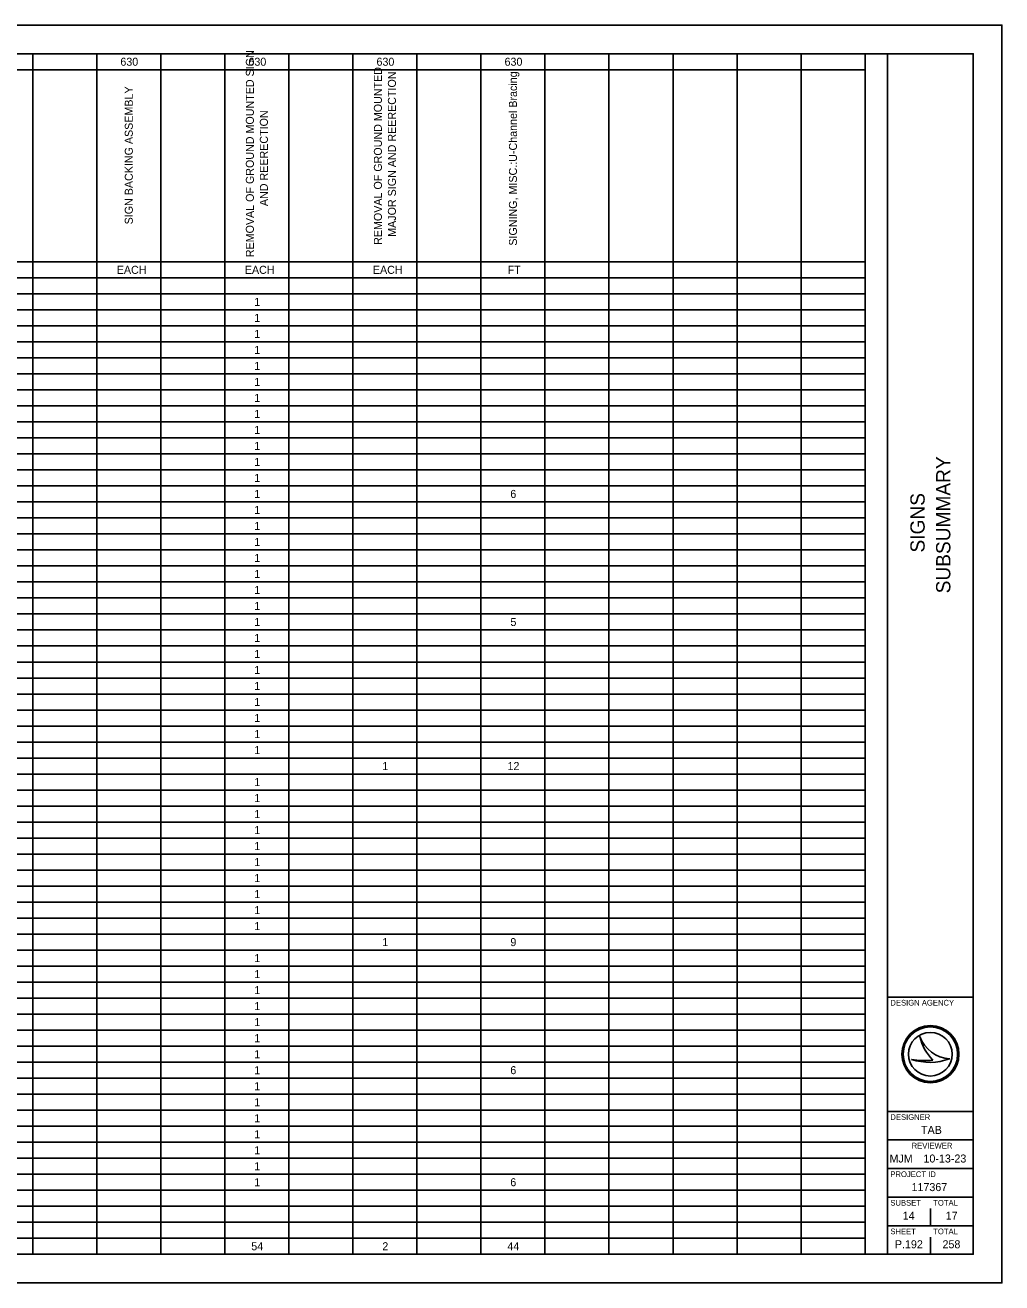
# Model space of a CAD drawing. Extents: x 0 to 34, y 0 to 22.
# Drawn here: x 16.92 to 34, y 0 to 22 of the extents above; entities that cross this region are included whole.
import ezdxf

# ---------------------------------------------------------------- set-up
doc = ezdxf.new("R2010")
doc.units = 0
for name, color, linetype in [('Default', 7, 'Continuous'), ('SH_Border', 7, 'Continuous'), ('SH_Cut_Line', 7, 'Continuous'), ('SH_Data', 7, 'Continuous')]:
    doc.layers.add(name, color=color, linetype=linetype)

msp = doc.modelspace()

# ---------------------------------------------------------------- linework, layer by layer
at = {"layer": 'Default'}
for p, q in [((1.5, 21.5), (31.608, 21.5)), ((17.048, 21.5), (17.048, 0.5)), ((18.168, 21.5), (18.168, 0.5)), ((19.288, 21.5), (19.288, 0.5)), ((20.408, 21.5), (20.408, 0.5)), ((21.528, 21.5), (21.528, 0.5)), ((22.648, 21.5), (22.648, 0.5)), ((23.768, 21.5), (23.768, 0.5)), ((24.888, 21.5), (24.888, 0.5)), ((26.008, 21.5), (26.008, 0.5)), ((27.128, 21.5), (27.128, 0.5)), ((28.248, 21.5), (28.248, 0.5)), ((29.368, 21.5), (29.368, 0.5)), ((30.488, 21.5), (30.488, 0.5)), ((31.608, 21.5), (31.608, 0.5)), ((8.681, 21.22), (31.608, 21.22)), ((8.681, 17.86), (31.608, 17.86)), ((1.5, 17.58), (31.608, 17.58)), ((1.5, 17.3), (31.608, 17.3)), ((1.5, 17.02), (31.608, 17.02)), ((1.5, 16.74), (31.608, 16.74)), ((1.5, 16.46), (31.608, 16.46)), ((1.5, 16.18), (31.608, 16.18)), ((1.5, 15.9), (31.608, 15.9)), ((1.5, 15.62), (31.608, 15.62)), ((1.5, 15.34), (31.608, 15.34)), ((1.5, 15.06), (31.608, 15.06)), ((1.5, 14.78), (31.608, 14.78)), ((1.5, 14.5), (31.608, 14.5)), ((1.5, 14.22), (31.608, 14.22)), ((1.5, 13.94), (31.608, 13.94)), ((1.5, 13.66), (31.608, 13.66)), ((1.5, 13.38), (31.608, 13.38)), ((1.5, 13.1), (31.608, 13.1)), ((1.5, 12.82), (31.608, 12.82)), ((1.5, 12.54), (31.608, 12.54)), ((1.5, 12.26), (31.608, 12.26)), ((1.5, 11.98), (31.608, 11.98)), ((1.5, 11.7), (31.608, 11.7)), ((1.5, 11.42), (31.608, 11.42)), ((1.5, 11.14), (31.608, 11.14)), ((1.5, 10.86), (31.608, 10.86)), ((1.5, 10.58), (31.608, 10.58)), ((1.5, 10.3), (31.608, 10.3)), ((1.5, 10.02), (31.608, 10.02)), ((1.5, 9.74), (31.608, 9.74)), ((1.5, 9.46), (31.608, 9.46)), ((1.5, 9.18), (31.608, 9.18)), ((1.5, 8.9), (31.608, 8.9)), ((1.5, 8.62), (31.608, 8.62)), ((1.5, 8.34), (31.608, 8.34)), ((1.5, 8.06), (31.608, 8.06)), ((1.5, 7.78), (31.608, 7.78)), ((1.5, 7.5), (31.608, 7.5)), ((1.5, 7.22), (31.608, 7.22)), ((1.5, 6.94), (31.608, 6.94)), ((1.5, 6.66), (31.608, 6.66)), ((1.5, 6.38), (31.608, 6.38)), ((1.5, 6.1), (31.608, 6.1)), ((1.5, 5.82), (31.608, 5.82)), ((1.5, 5.54), (31.608, 5.54)), ((1.5, 5.26), (31.608, 5.26)), ((1.5, 4.98), (31.608, 4.98)), ((1.5, 4.7), (31.608, 4.7)), ((1.5, 4.42), (31.608, 4.42)), ((1.5, 4.14), (31.608, 4.14)), ((1.5, 3.86), (31.608, 3.86)), ((1.5, 3.58), (31.608, 3.58)), ((1.5, 3.3), (31.608, 3.3)), ((1.5, 3.02), (31.608, 3.02)), ((1.5, 2.74), (31.608, 2.74)), ((1.5, 2.46), (31.608, 2.46)), ((1.5, 2.18), (31.608, 2.18)), ((1.5, 1.9), (31.608, 1.9)), ((1.5, 1.62), (31.608, 1.62)), ((1.5, 1.34), (31.608, 1.34)), ((1.5, 1.06), (31.608, 1.06)), ((1.5, 0.78), (31.608, 0.78)), ((1.5, 0.5), (31.608, 0.5))]:
    msp.add_line(p, q, dxfattribs=at)
at = {"layer": 'SH_Border'}
for p, q in [((32, 0.5), (32, 21.5)), ((32, 5), (33.5, 5)), ((32, 3), (33.5, 3)), ((32, 2.5), (33.5, 2.5)), ((32, 2), (33.5, 2)), ((32, 1.5), (33.5, 1.5)), ((32, 1), (33.5, 1))]:
    msp.add_line(p, q, dxfattribs=at)
msp.add_lwpolyline([(1.5, 21.5), (33.5, 21.5), (33.5, 0.5), (1.5, 0.5)], close=True, dxfattribs=at)
at = {"layer": 'SH_Cut_Line'}
msp.add_lwpolyline([(0, 0), (34, 0), (34, 22), (0, 22)], close=True, dxfattribs=at)
at = {"layer": 'SH_Data'}
for p, q in [((32.567, 4.31), (32.567, 4.31)), ((32.75, 4), (32.75, 4)), ((32.417, 3.91), (32.417, 3.91)), ((33.087, 3.919), (33.087, 3.919)), ((32.75, 1), (32.75, 1.3)), ((32.375, 0.675), (32.375, 0.675)), ((32.75, 0.5), (32.75, 0.8))]:
    msp.add_line(p, q, dxfattribs=at)
for radius in [0.5, 0.477, 0.477, 0.382]:
    msp.add_circle((32.75, 4), radius, dxfattribs=at)
for centre, radius, start, end in [((33.116, 4.498), 0.58, 198.9257, 198.9319), ((33.347, 4.47), 0.796, 191.6379, 191.6421), ((33.116, 4.498), 0.58, 198.9319, 267.1657), ((33.347, 4.47), 0.796, 191.6421, 226.0947), ((32.739, 4.87), 1.013, 251.4576, 290.0832), ((32.648, 5.154), 1.266, 259.4964, 259.4995), ((32.739, 4.87), 1.013, 251.4527, 251.4576), ((32.648, 5.154), 1.266, 259.4995, 276.6672)]:
    msp.add_arc(centre, radius, start, end, dxfattribs=at)

# ---------------------------------------------------------------- texts
at = {"layer": 'Default'}
for s, p in [('630', (18.581, 21.29)), ('630', (20.821, 21.29)), ('630', (23.061, 21.29)), ('630', (25.301, 21.29)), ('EACH', (18.518, 17.65)), ('EACH', (20.758, 17.65)), ('EACH', (22.998, 17.65)), ('FT', (25.355, 17.65)), ('1', (20.923, 17.09)), ('1', (20.923, 16.81)), ('1', (20.923, 16.53)), ('1', (20.923, 16.25)), ('1', (20.923, 15.97)), ('1', (20.923, 15.69)), ('1', (20.923, 15.41)), ('1', (20.923, 15.13)), ('1', (20.923, 14.85)), ('1', (20.923, 14.57)), ('1', (20.923, 14.29)), ('1', (20.923, 14.01)), ('1', (20.923, 13.73)), ('6', (25.402, 13.73)), ('1', (20.923, 13.45)), ('1', (20.923, 13.17)), ('1', (20.923, 12.89)), ('1', (20.923, 12.61)), ('1', (20.923, 12.33)), ('1', (20.923, 12.05)), ('1', (20.923, 11.77)), ('1', (20.923, 11.49)), ('5', (25.404, 11.49)), ('1', (20.923, 11.21)), ('1', (20.923, 10.93)), ('1', (20.923, 10.65)), ('1', (20.923, 10.37)), ('1', (20.923, 10.09)), ('1', (20.923, 9.81)), ('1', (20.923, 9.53)), ('1', (20.923, 9.25)), ('1', (23.163, 8.97)), ('12', (25.353, 8.97)), ('1', (20.923, 8.69)), ('1', (20.923, 8.41)), ('1', (20.923, 8.13)), ('1', (20.923, 7.85)), ('1', (20.923, 7.57)), ('1', (20.923, 7.29)), ('1', (20.923, 7.01)), ('1', (20.923, 6.73)), ('1', (20.923, 6.45)), ('1', (20.923, 6.17)), ('1', (23.163, 5.89)), ('9', (25.403, 5.89)), ('1', (20.923, 5.61)), ('1', (20.923, 5.33)), ('1', (20.923, 5.05)), ('1', (20.923, 4.77)), ('1', (20.923, 4.49)), ('1', (20.923, 4.21)), ('1', (20.923, 3.93)), ('1', (20.923, 3.65)), ('6', (25.402, 3.65)), ('1', (20.923, 3.37)), ('1', (20.923, 3.09)), ('1', (20.923, 2.81)), ('1', (20.923, 2.53)), ('1', (20.923, 2.25)), ('1', (20.923, 1.97)), ('1', (20.923, 1.69)), ('6', (25.402, 1.69)), ('54', (20.871, 0.57)), ('2', (23.163, 0.57)), ('44', (25.351, 0.57))]:
    msp.add_text(s, height=0.14, dxfattribs=at).set_placement(p)
for s, p in [('REMOVAL OF GROUND MOUNTED SIGN ', (20.916, 17.941)), ('REMOVAL OF GROUND MOUNTED ', (23.156, 18.157)), ('MAJOR SIGN AND REERECTION', (23.401, 18.298)), ('SIGNING, MISC.:U-Channel Bracing', (25.518, 18.143)), ('SIGN BACKING ASSEMBLY', (18.798, 18.515)), ('AND REERECTION', (21.161, 18.835))]:
    msp.add_text(s, height=0.14, rotation=90, dxfattribs=at).set_placement(p)
at = {"layer": 'SH_Data'}
for s, p in [('SUBSUMMARY', (33.1, 12.061)), ('SIGNS', (32.65, 12.775))]:
    msp.add_text(s, height=0.25, rotation=90, dxfattribs=at).set_placement(p)
for s, height, p in [('DESIGN AGENCY', 0.1, (32.05, 4.85)), ('DESIGNER', 0.1, (32.05, 2.85)), ('TAB', 0.14, (32.586, 2.605)), ('REVIEWER', 0.1, (32.422, 2.35)), ('MJM', 0.14, (32.035, 2.105)), ('10-13-23', 0.14, (32.629, 2.105)), ('PROJECT ID', 0.1, (32.05, 1.85)), ('117367', 0.14, (32.42, 1.605)), ('SUBSET', 0.1, (32.05, 1.35)), ('TOTAL', 0.1, (32.8, 1.35)), ('14', 0.14, (32.266, 1.105)), ('17', 0.14, (33.018, 1.105)), ('SHEET', 0.1, (32.05, 0.85)), ('TOTAL', 0.1, (32.8, 0.85)), ('P.192', 0.14, (32.129, 0.605)), ('258', 0.14, (32.962, 0.605))]:
    msp.add_text(s, height=height, dxfattribs=at).set_placement(p)

doc.saveas('drawing.dxf')
